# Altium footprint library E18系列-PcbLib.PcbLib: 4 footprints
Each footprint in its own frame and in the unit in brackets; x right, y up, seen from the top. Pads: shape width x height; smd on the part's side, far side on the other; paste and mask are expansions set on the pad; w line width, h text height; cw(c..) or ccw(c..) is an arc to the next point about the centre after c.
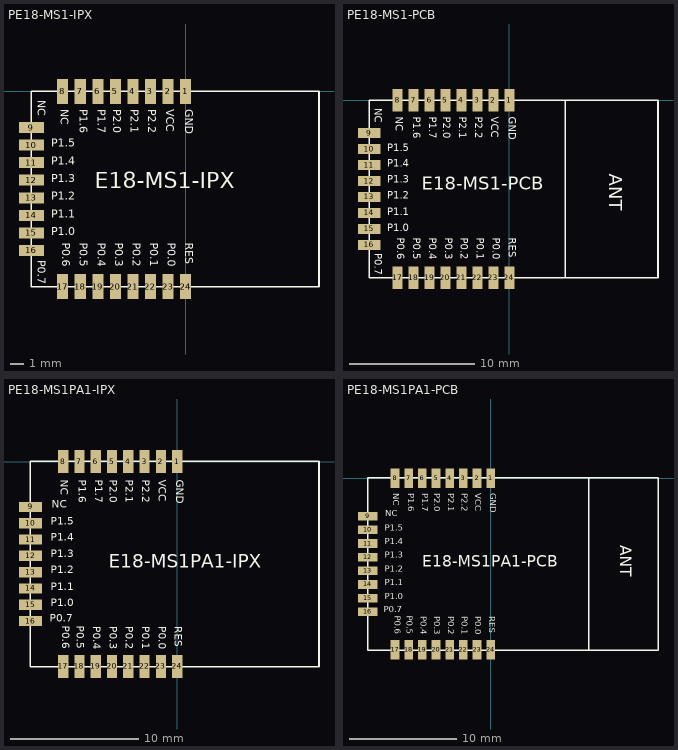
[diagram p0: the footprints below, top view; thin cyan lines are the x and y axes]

## PE18-MS1-IPX [mm] "20.8mm*14.1mm*2.40mm-S"
pads (24):
  rect 0.8x1.8 smd: 1(0,0) 2(-1.27,0) 3(-2.54,0) 4(-3.81,0) 5(-5.08,0) 6(-6.35,0) 7(-7.62,0) 8(-8.89,0) 17(-8.89,-14.114) 18(-7.62,-14.114) 19(-6.35,-14.114) 20(-5.08,-14.114) 21(-3.81,-14.114) 22(-2.54,-14.114) 23(-1.27,-14.114) 24(0,-14.114)
  rect 1.8x0.8 smd: 9(-11.146,-2.612) 10(-11.146,-3.882) 11(-11.146,-5.152) 12(-11.146,-6.422) 13(-11.146,-7.692) 14(-11.146,-8.962) 15(-11.146,-10.232) 16(-11.146,-11.502)
Top Overlay:
  lines w0.127: -11.158,-14.127 -11.158,0.013 9.642,0.013 9.642,-14.127 -11.158,-14.127
  text "E18-MS1-IPX" at -6.586,-7.396 h2
  text "GND" at -0.236,-1.3 h1
  text "VCC" at -1.633,-1.3 h1
  text "P2.2" at -2.903,-1.3 h1
  text "P2.1" at -4.173,-1.3 h1
  text "P2.0" at -5.443,-1.3 h1
  text "P1.7" at -6.586,-1.3 h1
  text "P1.6" at -7.856,-1.3 h1
  text "NC" at -10.922,-0.635 h1
  text "P0.6" at -9.126,-10.952 h1
  text "P0.5" at -7.856,-10.952 h1
  text "P0.4" at -6.586,-10.952 h1
  text "P0.3" at -5.316,-10.952 h1
  text "P0.2" at -4.046,-10.952 h1
  text "P0.1" at -2.776,-10.952 h1
  text "P0.0" at -1.506,-10.952 h1
  text "RES" at -0.236,-10.952 h1
  text "NC" at -9.253,-1.3 h1
  text "P1.5" at -9.723,-4.233 h1
  text "P1.4" at -9.723,-5.503 h1
  text "P1.3" at -9.723,-6.773 h1
  text "P1.2" at -9.723,-8.043 h1
  text "P1.1" at -9.723,-9.339 h1
  text "P1.0" at -9.723,-10.609 h1
  text "P0.7" at -10.922,-12.192 h1

## PE18-MS1-PCB [mm] "23mm*14.1mm*2.40mm-S"
pads (24):
  rect 0.8x1.8 smd: 1(0,0) 2(-1.27,0) 3(-2.54,0) 4(-3.81,0) 5(-5.08,0) 6(-6.35,0) 7(-7.62,0) 8(-8.89,0) 17(-8.89,-14.114) 18(-7.62,-14.114) 19(-6.35,-14.114) 20(-5.08,-14.114) 21(-3.81,-14.114) 22(-2.54,-14.114) 23(-1.27,-14.114) 24(0,-14.114)
  rect 1.8x0.8 smd: 9(-11.146,-2.612) 10(-11.146,-3.882) 11(-11.146,-5.152) 12(-11.146,-6.422) 13(-11.146,-7.692) 14(-11.146,-8.962) 15(-11.146,-10.232) 16(-11.146,-11.502)
Top Overlay:
  lines w0.127: 4.445,-14.127 4.445,0 ; 11.842,0 11.842,-14.127 -11.158,-14.127 -11.158,0.013 11.842,0.013
  text "E18-MS1-PCB" at -6.985,-7.493 h1.8
  text "GND" at -0.236,-1.3 h1
  text "VCC" at -1.633,-1.3 h1
  text "P2.2" at -2.903,-1.3 h1
  text "P2.1" at -4.173,-1.3 h1
  text "P2.0" at -5.443,-1.3 h1
  text "P1.7" at -6.586,-1.3 h1
  text "P1.6" at -7.856,-1.3 h1
  text "NC" at -10.922,-0.635 h1
  text "P0.6" at -9.126,-10.952 h1
  text "P0.5" at -7.856,-10.952 h1
  text "P0.4" at -6.586,-10.952 h1
  text "P0.3" at -5.316,-10.952 h1
  text "P0.2" at -4.046,-10.952 h1
  text "P0.1" at -2.776,-10.952 h1
  text "P0.0" at -1.506,-10.952 h1
  text "RES" at -0.236,-10.952 h1
  text "NC" at -9.253,-1.3 h1
  text "P1.5" at -9.723,-4.233 h1
  text "P1.4" at -9.723,-5.503 h1
  text "P1.3" at -9.723,-6.773 h1
  text "P1.2" at -9.723,-8.043 h1
  text "P1.1" at -9.723,-9.339 h1
  text "P1.0" at -9.723,-10.609 h1
  text "P0.7" at -10.922,-12.192 h1
  text "ANT" at 7.62,-5.842 h1.8

## PE18-MS1PA1-IPX [mm] "22.5mm*16mm*2.40mm-S"
pads (24):
  rect 0.8x1.8 smd: 1(0,0) 2(-1.27,0) 3(-2.54,0) 4(-3.81,0) 5(-5.08,0) 6(-6.35,0) 7(-7.62,0) 8(-8.89,0) 17(-8.89,-15.975) 18(-7.62,-15.975) 19(-6.35,-15.975) 20(-5.08,-15.975) 21(-3.81,-15.975) 22(-2.54,-15.975) 23(-1.27,-15.975) 24(0,-15.975)
  rect 1.8x0.8 smd: 9(-11.432,-3.542) 10(-11.432,-4.812) 11(-11.432,-6.082) 12(-11.432,-7.352) 13(-11.432,-8.622) 14(-11.432,-9.892) 15(-11.432,-11.162) 16(-11.432,-12.432)
Top Overlay:
  lines w0.127: -11.445,-15.987 -11.445,0.013 11.055,0.013 11.055,-15.987 -11.445,-15.987
  text "P0.7" at -9.921,-12.685 h1
  text "P1.0" at -9.865,-11.483 h1
  text "P1.1" at -9.865,-10.213 h1
  text "P1.2" at -9.865,-8.918 h1
  text "P1.3" at -9.865,-7.648 h1
  text "P1.4" at -9.865,-6.378 h1
  text "P1.5" at -9.865,-5.108 h1
  text "NC" at -9.268,-1.412 h1
  text "RES" at -0.378,-12.842 h1
  text "P0.0" at -1.648,-12.842 h1
  text "P0.1" at -2.918,-12.842 h1
  text "P0.2" at -4.188,-12.842 h1
  text "P0.3" at -5.458,-12.842 h1
  text "P0.4" at -6.728,-12.842 h1
  text "P0.5" at -8.016,-12.812 h1
  text "P0.6" at -9.159,-12.812 h1
  text "NC" at -9.794,-3.795 h1
  text "P1.6" at -7.871,-1.412 h1
  text "P1.7" at -6.601,-1.412 h1
  text "P2.0" at -5.458,-1.412 h1
  text "P2.1" at -4.188,-1.412 h1
  text "P2.2" at -2.918,-1.412 h1
  text "VCC" at -1.648,-1.412 h1
  text "GND" at -0.251,-1.412 h1
  text "E18-MS1PA1-IPX" at -5.349,-8.621 h1.8

## PE18-MS1PA1-PCB [mm] "27mm*16mm*2.40mm-S"
pads (24):
  rect 0.8x1.8 smd: 1(0,0) 2(-1.27,0) 3(-2.54,0) 4(-3.81,0) 5(-5.08,0) 6(-6.35,0) 7(-7.62,0) 8(-8.89,0) 17(-8.89,-15.975) 18(-7.62,-15.975) 19(-6.35,-15.975) 20(-5.08,-15.975) 21(-3.81,-15.975) 22(-2.54,-15.975) 23(-1.27,-15.975) 24(0,-15.975)
  rect 1.8x0.8 smd: 9(-11.432,-3.542) 10(-11.432,-4.812) 11(-11.432,-6.082) 12(-11.432,-7.352) 13(-11.432,-8.622) 14(-11.432,-9.892) 15(-11.432,-11.162) 16(-11.432,-12.432)
Top Overlay:
  lines w0.127: 9.115,-15.987 9.115,0.013 ; -11.445,-15.987 15.555,-15.987 15.555,0.013 -11.445,0.013 -11.445,-15.987
  text "E18-MS1PA1-PCB" at -6.35,-8.636 h1.8
  text "GND" at -0.251,-1.412 h1
  text "VCC" at -1.648,-1.412 h1
  text "P2.2" at -2.918,-1.412 h1
  text "P2.1" at -4.188,-1.412 h1
  text "P2.0" at -5.458,-1.412 h1
  text "P1.7" at -6.601,-1.412 h1
  text "P1.6" at -7.871,-1.412 h1
  text "NC" at -9.794,-3.795 h1
  text "P0.6" at -9.159,-12.812 h1
  text "P0.5" at -8.016,-12.812 h1
  text "P0.4" at -6.728,-12.842 h1
  text "P0.3" at -5.458,-12.842 h1
  text "P0.2" at -4.188,-12.842 h1
  text "P0.1" at -2.918,-12.842 h1
  text "P0.0" at -1.648,-12.842 h1
  text "RES" at -0.378,-12.842 h1
  text "NC" at -9.268,-1.412 h1
  text "P1.5" at -9.865,-5.108 h1
  text "P1.4" at -9.865,-6.378 h1
  text "P1.3" at -9.865,-7.648 h1
  text "P1.2" at -9.865,-8.918 h1
  text "P1.1" at -9.865,-10.213 h1
  text "P1.0" at -9.865,-11.483 h1
  text "P0.7" at -9.921,-12.685 h1
  text "ANT" at 11.684,-6.223 h1.8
